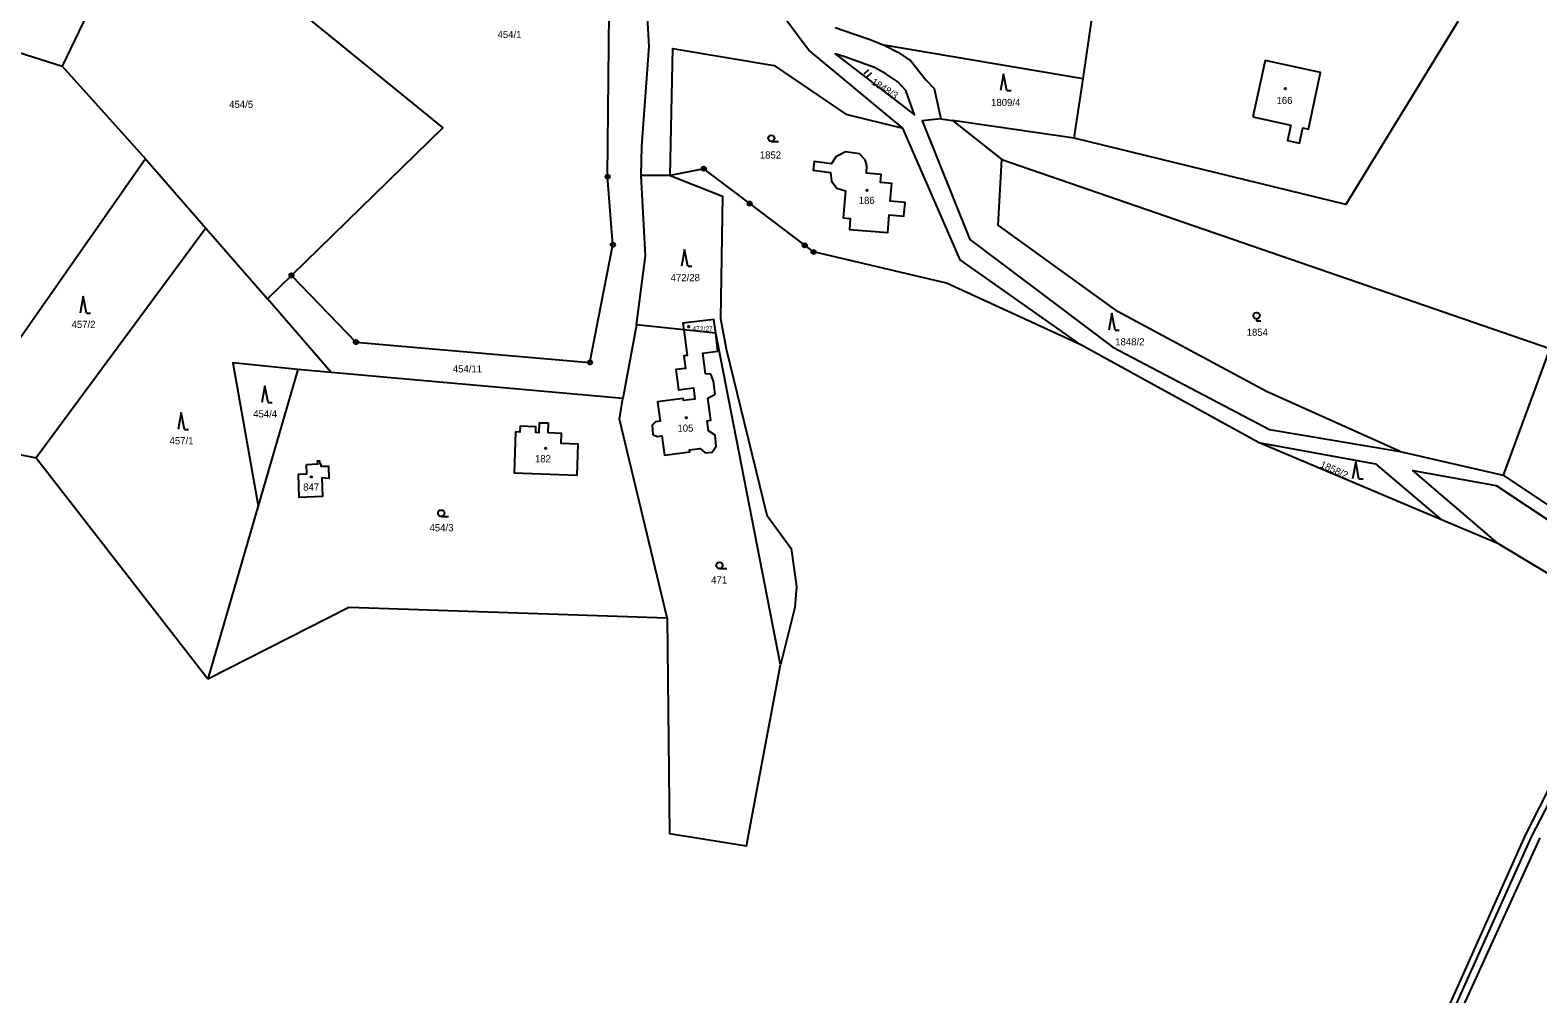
# Model space of a CAD drawing. Extents: x -725728 to -720881, y -1068679 to -1063504.
# Drawn here: x -723450.7 to -723092.7, y -1067751.9 to -1067523 of the extents above; entities that cross this region are included whole.
import ezdxf

# ---------------------------------------------------------------- set-up
doc = ezdxf.new("R2010")
doc.units = 0
for name, color, linetype in [('Hranice parcel', 7, 'Continuous'), ('Parcelní čísla', 7, 'Continuous'), ('Značky bodu BP', 7, 'Continuous'), ('Značky budov', 7, 'Continuous'), ('Značky kultur', 7, 'Continuous')]:
    doc.layers.add(name, color=color, linetype=linetype)

# ---------------------------------------------------------------- blocks, each defined once
blk = doc.blocks.new('4.02_3')
at = {"layer": 'Značky budov'}
blk.add_circle((-0.001, 0), 0.0175, dxfattribs=at)
blk = doc.blocks.new('4.02_4')
at = {"layer": 'Značky budov'}
blk.add_circle((-0.001, 0), 0.0175, dxfattribs=at)
blk = doc.blocks.new('3.04_2')
at = {"layer": 'Značky kultur'}
blk.add_line((0.001, 0), (0.176, 0), dxfattribs=at)
blk.add_circle((0.001, 0.075), 0.075, dxfattribs=at)
blk = doc.blocks.new('3.08_2')
at = {"layer": 'Značky kultur'}
for p, q in [((0, 0.4), (-0.075, 0)), ((0.075, 0), (0, 0.4)), ((0.075, 0), (0.175, 0))]:
    blk.add_line(p, q, dxfattribs=at)
blk = doc.blocks.new('3.08_1')
at = {"layer": 'Značky kultur'}
for p, q in [((0, 0.4), (-0.075, 0)), ((0.075, 0), (0, 0.4)), ((0.075, 0), (0.175, 0))]:
    blk.add_line(p, q, dxfattribs=at)
blk = doc.blocks.new('1.05_1')
at = {"layer": 'Značky bodu BP'}
for radius in [0.05, 0.00303]:
    blk.add_circle((0, 0), radius, dxfattribs=at)
blk = doc.blocks.new('1.05_2')
at = {"layer": 'Značky bodu BP'}
for radius in [0.05, 0.00303]:
    blk.add_circle((0, 0), radius, dxfattribs=at)

msp = doc.modelspace()

# ---------------------------------------------------------------- linework, layer by layer
at = {"layer": 'Hranice parcel'}
for p, q in [((-723200.73, -1067534.53), (-723192.46, -1067478.32)), ((-723423.82, -1067491.11), (-723443.13, -1067531.53)), ((-723259.6, -1067522.35), (-723255.26, -1067523.82)), ((-723466.08, -1067524.22), (-723443.13, -1067531.53)), ((-723200.73, -1067534.53), (-723247.95, -1067526.51)), ((-723443.13, -1067531.53), (-723423.31, -1067553.51)), ((-723202.81, -1067548.65), (-723200.73, -1067534.53)), ((-723234.53, -1067544.03), (-723231.73, -1067544.44)), ((-723202.81, -1067548.65), (-723231.73, -1067544.44)), ((-723231.73, -1067544.44), (-723220.03, -1067553.72)), ((-723423.31, -1067553.51), (-723470.12, -1067620.43)), ((-723423.31, -1067553.51), (-723409, -1067569.99)), ((-723298.73, -1067557.5), (-723305.62, -1067557.5)), ((-723298.73, -1067557.5), (-723305.62, -1067557.5)), ((-723409, -1067569.99), (-723449.27, -1067624.52)), ((-723409, -1067569.99), (-723394.41, -1067586.81)), ((-723394.41, -1067586.81), (-723388.69, -1067581.22)), ((-723388.69, -1067581.22), (-723373.39, -1067597.06)), ((-723379.26, -1067604.28), (-723394.41, -1067586.81)), ((-723306.76, -1067592.97), (-723309.98, -1067610.43)), ((-723295.54, -1067594.14), (-723306.76, -1067592.97)), ((-723287.94, -1067594.93), (-723295.54, -1067594.14)), ((-723272.58, -1067673.75), (-723287.94, -1067594.93)), ((-723159.09, -1067620.93), (-723201.27, -1067597.74)), ((-723159.09, -1067620.93), (-723201.27, -1067597.74)), ((-723387.15, -1067603.58), (-723396.57, -1067635.93)), ((-723379.26, -1067604.28), (-723387.15, -1067603.58)), ((-723309.98, -1067610.43), (-723379.26, -1067604.28)), ((-723470.12, -1067620.43), (-723449.27, -1067624.52)), ((-723115.63, -1067639.28), (-723159.09, -1067620.93)), ((-723115.63, -1067639.28), (-723159.09, -1067620.93)), ((-723449.27, -1067624.52), (-723408.53, -1067677.01)), ((-723125.42, -1067623.04), (-723100.95, -1067628.7)), ((-723396.57, -1067635.93), (-723408.53, -1067677.01)), ((-723102.1, -1067644.99), (-723115.63, -1067639.28)), ((-723102.1, -1067644.99), (-723115.63, -1067639.28)), ((-723067.52, -1067665.83), (-723102.1, -1067644.99)), ((-723067.52, -1067665.83), (-723102.1, -1067644.99)), ((-723094.26, -1067714.56), (-723084.33, -1067695.39)), ((-723094.26, -1067714.56), (-723084.33, -1067695.39))]:
    msp.add_line(p, q, dxfattribs=at)
for points in [[(-723373.39, -1067597.06), (-723317.82, -1067601.89), (-723312.36, -1067573.95), (-723313.62, -1067557.76), (-723313.08, -1067503.08), (-723313.22, -1067496.73), (-723321.81, -1067476.24), (-723334.84, -1067460.54)], [(-723305.62, -1067557.5), (-723305.53, -1067550.56), (-723303.74, -1067526.82), (-723305.08, -1067503.03), (-723305.25, -1067495.04), (-723305.06, -1067489.23), (-723315.28, -1067469.63)], [(-723305.62, -1067557.5), (-723305.53, -1067550.56), (-723303.74, -1067526.82), (-723305.08, -1067503.03), (-723305.25, -1067495.04), (-723305.06, -1067489.23), (-723315.28, -1067469.63)], [(-723139.95, -1067484.12), (-723112.82, -1067492.34), (-723111.81, -1067521.09), (-723138.31, -1067564.35), (-723202.81, -1067548.65)], [(-723419.68, -1067491.6), (-723352.75, -1067546.16), (-723388.69, -1067581.22)], [(-723243.52, -1067546.28), (-723265.85, -1067527.69), (-723266.91, -1067526.27), (-723273.33, -1067517.67)], [(-723255.26, -1067523.82), (-723251.5, -1067525.13), (-723247.95, -1067526.51)], [(-723298.73, -1067557.5), (-723298.13, -1067527.34), (-723274.08, -1067531.38), (-723257.03, -1067542.94), (-723243.52, -1067546.28)], [(-723250.28, -1067531.8), (-723257.33, -1067529.26), (-723259.62, -1067528.57), (-723240.78, -1067543.09), (-723242.8, -1067537.28), (-723244.73, -1067535.24), (-723247.57, -1067533.31), (-723250.28, -1067531.8)], [(-723247.95, -1067526.51), (-723244.74, -1067528.15), (-723241.61, -1067530.25), (-723238.07, -1067534.73), (-723236.11, -1067536.84), (-723234.53, -1067544.03)], [(-723160.42, -1067543.57), (-723151.37, -1067545.54), (-723152.16, -1067549.2), (-723149.37, -1067549.8), (-723148.57, -1067546.15), (-723147.23, -1067546.44), (-723144.33, -1067533.05), (-723157.52, -1067530.19), (-723160.42, -1067543.57)], [(-723234.53, -1067544.03), (-723238.93, -1067544.51), (-723227.61, -1067572.69), (-723193.65, -1067598.24), (-723156.48, -1067617.84), (-723125.42, -1067623.04)], [(-723201.27, -1067597.74), (-723229.91, -1067577.5), (-723243.52, -1067546.28)], [(-723260.44, -1067558.87), (-723259.22, -1067560.52), (-723257.13, -1067561.16), (-723257.66, -1067567.55), (-723256.01, -1067567.68), (-723256.22, -1067570.28), (-723247.11, -1067571.02), (-723246.77, -1067566.83), (-723243.26, -1067567.12), (-723243, -1067563.9), (-723246.51, -1067563.61), (-723246.17, -1067559.37), (-723248.8, -1067559.16), (-723248.65, -1067557.22), (-723252.14, -1067556.93), (-723252.08, -1067555.12), (-723252.43, -1067553.77), (-723253.78, -1067552.33), (-723257.17, -1067551.9), (-723259.44, -1067553.07), (-723260.44, -1067554.68), (-723264.58, -1067554.16), (-723264.84, -1067556.24), (-723260.7, -1067556.76), (-723260.44, -1067558.87)], [(-723125.42, -1067623.04), (-723157.15, -1067608.82), (-723192.41, -1067589.84), (-723220.88, -1067569.32), (-723220.03, -1067553.72)], [(-723220.03, -1067553.72), (-723089.93, -1067598.55), (-723100.95, -1067628.7)], [(-723306.76, -1067592.97), (-723304.63, -1067576.53), (-723305.62, -1067557.5)], [(-723264.73, -1067575.65), (-723266.81, -1067574.07), (-723279.88, -1067564.14), (-723290.78, -1067555.87), (-723298.73, -1067557.5)], [(-723264.73, -1067575.65), (-723266.81, -1067574.07), (-723279.88, -1067564.14), (-723290.78, -1067555.87), (-723298.73, -1067557.5)], [(-723298.73, -1067557.5), (-723286.31, -1067562.37), (-723286.82, -1067591.44), (-723285.49, -1067598.65), (-723275.82, -1067638.17), (-723270.01, -1067646.11), (-723268.73, -1067655.11), (-723269.13, -1067660.13), (-723272.58, -1067673.75)], [(-723201.27, -1067597.74), (-723233.16, -1067583.1), (-723264.73, -1067575.65)], [(-723201.27, -1067597.74), (-723233.16, -1067583.1), (-723264.73, -1067575.65)], [(-723100.95, -1067628.7), (-723072.64, -1067647.6), (-723064.41, -1067651.13), (-723058.72, -1067651.33), (-723050.68, -1067645.96), (-723032.31, -1067629.23), (-723021.66, -1067622.95), (-723003.89, -1067614.12), (-722973.3, -1067601.12), (-722952.86, -1067586.47), (-722947.2, -1067583.41), (-722934.08, -1067577.18)], [(-723295.54, -1067594.14), (-723294.76, -1067600.23), (-723295.54, -1067600.33), (-723295.16, -1067603.3), (-723297.39, -1067603.59), (-723296.77, -1067608.4), (-723293.25, -1067607.95), (-723292.91, -1067610.58), (-723295.63, -1067610.93), (-723295.69, -1067610.48), (-723301.75, -1067611.26), (-723301.16, -1067615.84), (-723302.21, -1067615.97), (-723303.04, -1067616.76), (-723302.92, -1067619), (-723301.89, -1067619.47), (-723300.72, -1067619.32), (-723300.13, -1067623.91), (-723294.13, -1067623.15), (-723294.19, -1067622.65), (-723291.67, -1067622.33), (-723290.43, -1067623.33), (-723288.83, -1067623.2), (-723287.84, -1067621.76), (-723288.09, -1067619.15), (-723289.63, -1067618.1), (-723289.95, -1067615.73), (-723289.13, -1067615.62), (-723289.85, -1067610.34), (-723288.12, -1067609.44), (-723288.51, -1067606.37), (-723289.08, -1067604.65), (-723290.37, -1067604.61), (-723291, -1067599.7), (-723287.42, -1067599.24), (-723287.94, -1067594.93)], [(-723287.94, -1067594.93), (-723288.4, -1067591.66), (-723295.74, -1067592.6), (-723295.54, -1067594.14)], [(-723387.15, -1067603.58), (-723402.6, -1067601.97), (-723396.57, -1067635.93)], [(-723299.44, -1067662.54), (-723310.76, -1067615.37), (-723309.98, -1067610.43)], [(-723327.65, -1067616.35), (-723329.85, -1067616.28), (-723329.93, -1067618.58), (-723330.68, -1067618.56), (-723330.63, -1067617.16), (-723334.38, -1067617.03), (-723334.43, -1067618.43), (-723335.52, -1067618.4), (-723335.84, -1067628.14), (-723320.88, -1067628.63), (-723320.64, -1067621.27), (-723324.66, -1067621.14), (-723324.58, -1067618.75), (-723327.73, -1067618.65), (-723327.65, -1067616.35)], [(-723159.09, -1067620.93), (-723131.26, -1067625.97), (-723115.63, -1067639.28)], [(-723385.14, -1067626.1), (-723382.45, -1067626.01), (-723382.48, -1067625.29), (-723382.02, -1067625.28), (-723381.99, -1067626), (-723381.7, -1067625.99), (-723381.69, -1067626.55), (-723379.87, -1067626.5), (-723379.78, -1067629.49), (-723381.44, -1067629.34), (-723381.29, -1067633.76), (-723386.83, -1067633.95), (-723387.01, -1067628.41), (-723385.07, -1067628.34), (-723385.14, -1067626.1)], [(-723102.1, -1067644.99), (-723122.43, -1067627.57), (-723102.63, -1067631.15), (-723073.72, -1067650.28), (-723066.37, -1067654.11), (-723056.89, -1067654.65)], [(-723408.53, -1067677.01), (-723375.04, -1067660.03), (-723299.44, -1067662.54)], [(-723299.44, -1067662.54), (-723298.95, -1067713.81), (-723280.65, -1067716.75), (-723272.58, -1067673.75)], [(-723040.57, -1068018.44), (-723041.45, -1068020.15), (-723053.84, -1068009.4), (-723063.01, -1067989.69), (-723068.96, -1067963.47), (-723082.51, -1067937.46), (-723117.57, -1067885.77), (-723133.55, -1067852.16), (-723146.34, -1067824.42), (-723143.95, -1067807.38), (-723131.43, -1067783.07), (-723114.25, -1067755.83), (-723095.64, -1067714.22), (-723085.72, -1067694.44), (-723067.52, -1067665.83)], [(-723092.23, -1067714.85), (-723110.84, -1067755.63), (-723126.94, -1067781.78), (-723139.93, -1067807.34), (-723143.18, -1067823.44), (-723131.07, -1067851.95), (-723114.38, -1067885.05), (-723080.12, -1067934.54), (-723068.54, -1067955.25)], [(-723142.36, -1067807.84), (-723130.16, -1067784.13), (-723113.08, -1067756.58), (-723094.26, -1067714.56)], [(-723142.36, -1067807.84), (-723130.16, -1067784.13), (-723113.08, -1067756.58), (-723094.26, -1067714.56)]]:
    msp.add_lwpolyline(points, dxfattribs=at)
at = {"layer": 'Značky bodu BP'}
for centre, radius in [((-723290.78, -1067555.87), 0.5), ((-723290.78, -1067555.87), 0.0303), ((-723279.88, -1067564.14), 0.5), ((-723279.88, -1067564.14), 0.0303), ((-723266.81, -1067574.07), 0.5), ((-723266.81, -1067574.07), 0.0303), ((-723264.73, -1067575.65), 0.5), ((-723264.73, -1067575.65), 0.0303)]:
    msp.add_circle(centre, radius, dxfattribs=at)
at = {"layer": 'Značky budov'}
for centre in [(-723152.67, -1067536.87), (-723252, -1067561)]:
    msp.add_circle(centre, 0.175, dxfattribs=at)
at = {"layer": 'Značky kultur'}
for p, q in [((-723252.69, -1067533.36), (-723251.61, -1067532.32)), ((-723251.99, -1067534.08), (-723250.91, -1067533.04)), ((-723219.58, -1067533.31), (-723220.33, -1067537.31)), ((-723218.83, -1067537.31), (-723219.58, -1067533.31)), ((-723218.83, -1067537.31), (-723217.83, -1067537.31)), ((-723274.76, -1067549.39), (-723273.01, -1067549.39)), ((-723193.88, -1067590.21), (-723194.63, -1067594.21)), ((-723193.13, -1067594.21), (-723193.88, -1067590.21)), ((-723159.54, -1067591.53), (-723159.54, -1067592.03)), ((-723159.54, -1067592.03), (-723158.54, -1067592.03)), ((-723193.13, -1067594.21), (-723192.13, -1067594.21)), ((-723135.99, -1067625.51), (-723136.74, -1067629.51)), ((-723135.24, -1067629.51), (-723135.99, -1067625.51)), ((-723135.24, -1067629.51), (-723134.24, -1067629.51))]:
    msp.add_line(p, q, dxfattribs=at)
for centre in [(-723274.76, -1067548.64), (-723159.54, -1067590.78)]:
    msp.add_circle(centre, 0.75, dxfattribs=at)

# ---------------------------------------------------------------- block references
at = {"layer": 'Značky bodu BP', "xscale": 10, "yscale": 10}
for name, p in [('1.05_1', (-723313.62, -1067557.76)), ('1.05_1', (-723312.36, -1067573.95)), ('1.05_1', (-723388.69, -1067581.22)), ('1.05_1', (-723373.39, -1067597.06)), ('1.05_2', (-723317.82, -1067601.89))]:
    msp.add_blockref(name, p, dxfattribs=at)
at = {"layer": 'Značky budov', "xscale": 10, "yscale": 10}
for name, p in [('4.02_4', (-723294.35, -1067593.38)), ('4.02_3', (-723294.92, -1067615.03)), ('4.02_3', (-723328.29, -1067622.29)), ('4.02_3', (-723383.99, -1067629.07))]:
    msp.add_blockref(name, p, dxfattribs=at)
at = {"layer": 'Značky kultur', "xscale": 10, "yscale": 10}
for name, p in [('3.08_1', (-723295.35, -1067579.04)), ('3.08_2', (-723438.14, -1067590.15)), ('3.08_2', (-723395.01, -1067611.41)), ('3.08_1', (-723414.87, -1067617.79)), ('3.04_2', (-723353.14, -1067638.45)), ('3.04_2', (-723287.07, -1067650.86))]:
    msp.add_blockref(name, p, dxfattribs=at)

# ---------------------------------------------------------------- texts
at = {"layer": 'Parcelní čísla'}
for s, height, p in [('454/1', 1.7, (-723339.76, -1067524.84)), ('454/5', 1.7, (-723403.48, -1067541.43)), ('1809/4', 1.7, (-723222.57, -1067540.99)), ('166', 1.7, (-723154.8, -1067540.5)), ('1852', 1.7, (-723277.48, -1067553.46)), ('186', 1.7, (-723254, -1067564.25)), ('472/28', 1.7, (-723298.65, -1067582.59)), ('457/2', 1.7, (-723440.91, -1067593.7)), ('472/27', 1.14, (-723293.48, -1067594.48)), ('1854', 1.7, (-723161.88, -1067595.57)), ('1848/2', 1.7, (-723193.09, -1067597.84)), ('454/11', 1.7, (-723350.38, -1067604.27)), ('454/4', 1.7, (-723397.78, -1067614.96)), ('105', 1.7, (-723297.04, -1067618.34)), ('457/1', 1.7, (-723417.64, -1067621.34)), ('182', 1.7, (-723330.88, -1067625.61)), ('847', 1.7, (-723385.91, -1067632.34)), ('454/3', 1.7, (-723355.91, -1067642)), ('471', 1.7, (-723289.04, -1067654.41))]:
    msp.add_text(s, height=height, dxfattribs=at).set_placement(p)
for s, rotation, p in [('1848/3', 327, (-723251.2, -1067535.65)), ('1858/2', 336, (-723144.61, -1067626.74))]:
    msp.add_text(s, height=1.7, rotation=rotation, dxfattribs=at).set_placement(p)

doc.saveas('drawing.dxf')
